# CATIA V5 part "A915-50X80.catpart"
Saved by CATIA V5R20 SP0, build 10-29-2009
Part number: A915-50X80
Source: Unknown
Property "A": "0.000"
Property "ARTICLENO": "A915-50X80"
Property "BOMINFO": "A915-50X80"
Property "CODE": "A915-50X80"
Property "CREATOR": "CADENAS GmbH"
Property "D": "9.000"
Property "D1": "15.000"
Property "FORM": "B"
Property "L": "80.000"
Property "L1": "25.000"
Property "L2": "30.000"
Property "LINA": "A915-50X80"
Property "NB": "A915-50X80"
Property "NBSYN": "$CODE."
Property "NN": "A915"
Property "NT": "VDI 3357 Wear Plates, steel"
Property "SCREW": "M8x25"
Property "SUPPLIER": "CF"
Property "T": "9.000"
Property "W": "50.000"
Bounding box of the stored display mesh (mm): x 0 to 20, y 0 to 80, z -25 to 25
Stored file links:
  C:\Users\borellobunino\Desktop\3D X SITO CF\A915\GSB_OILLESS_G22501050080\A915-50X80.catpart
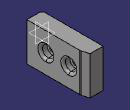
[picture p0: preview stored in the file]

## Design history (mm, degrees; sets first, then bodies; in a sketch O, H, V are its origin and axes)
Body1 "Geometry.1" (main body)
  Solid1 "A915-50X80.catpart": solid without history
